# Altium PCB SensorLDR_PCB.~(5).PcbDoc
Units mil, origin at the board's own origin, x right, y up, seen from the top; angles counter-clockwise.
Board outline 6000 x 4000 mil, 2 copper layers (Top Layer, Bottom Layer); 24 components, 17 nets, 62 pads, 0 vias.
Unrouted connection lines stored in the file: 38.
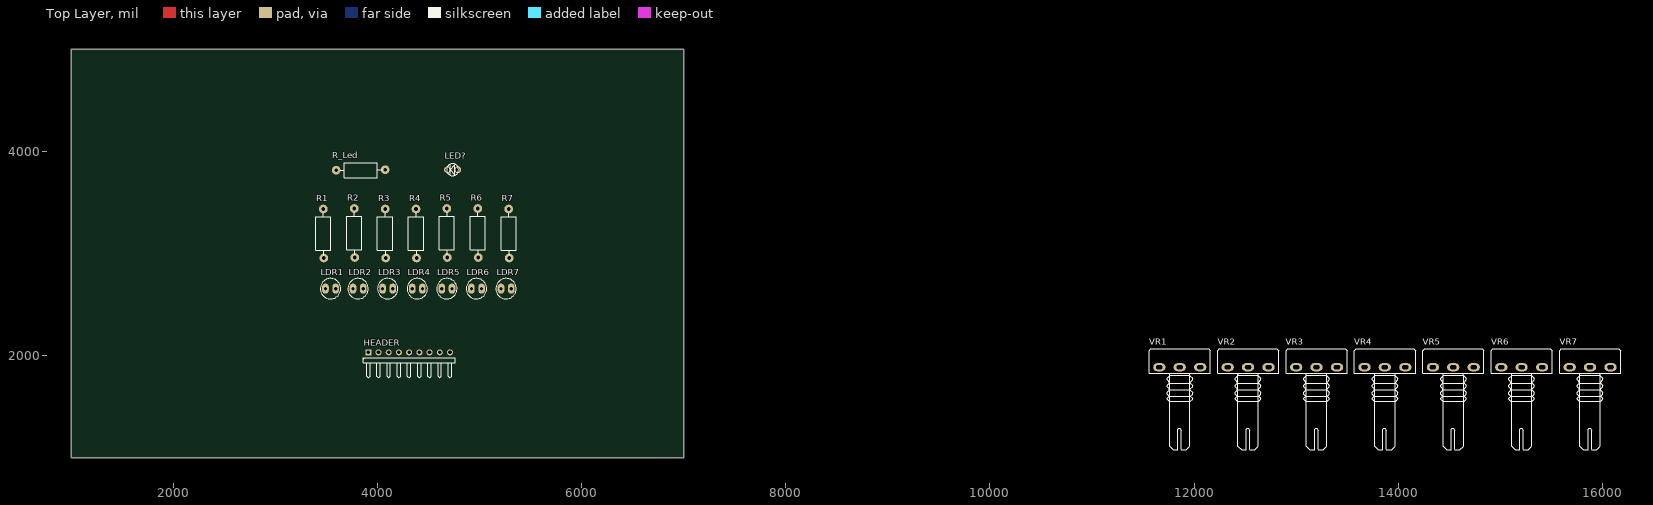
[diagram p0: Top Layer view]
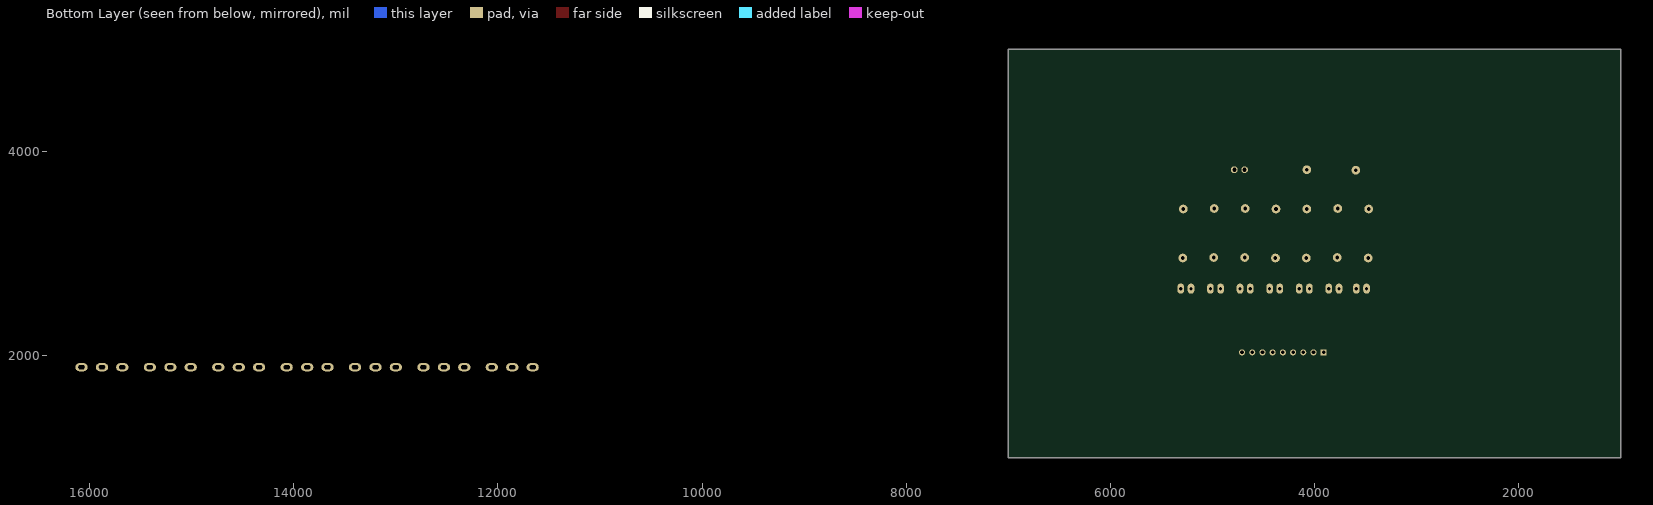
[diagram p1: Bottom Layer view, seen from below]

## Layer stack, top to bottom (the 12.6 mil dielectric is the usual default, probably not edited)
Top Solder: solder mask 0.4, Solder Resist, Dk 3.5
Top Layer: signal copper 1.4
Dielectric 1: dielectric 12.6, FR-4, Dk 4.8
Bottom Layer: signal copper 1.4
Bottom Solder: solder mask 0.4, Solder Resist, Dk 3.5

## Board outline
1000,1000 7000,1000 7000,5000 1000,5000

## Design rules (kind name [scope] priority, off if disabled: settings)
Clearance [All] p1: gap=10 ignorepadtopadclearanceinfootprint=FALSE except(0: Arc-Hole Track-Hole SMDPad-Hole THPad-Hole Via-Hole Fill-Hole Poly-Hole Region-Hole Text-Hole)
PolygonConnect [All] p1: connectstyle=Relief reliefconductorwidth=10 reliefentries=4 polygonreliefangle="90 Angle" airgapwidth=10
RoutingVias [All] p1: holewidth=28 width=50 viastyle="Through Hole" minholewidth=28 minwidth=50 maxholewidth=28 maxwidth=50
SolderMaskExpansion [All] p1: expansion=4
Width [All] p1: maxlimit=10 minlimit=10 preferedwidth=10
30 further rules are at their usual default settings.

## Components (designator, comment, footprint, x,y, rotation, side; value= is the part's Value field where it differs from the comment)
HEADER "Header 9H" HDR1X9H 3910,2030 r0 top
LDR1 "LDR" CDS 3490,2655 r0 top
LDR2 "LDR" CDS 3760,2655 r0 top
LDR3 "LDR" CDS 4050,2655 r0 top
LDR4 "LDR" CDS 4340,2655 r0 top
LDR5 "LDR" CDS 4630,2655 r0 top
LDR6 "LDR" CDS 4920,2655 r0 top
LDR7 "LDR" CDS 5210,2655 r0 top
LED? "LED" LED-3MM-YELLOW 4785,3820 r180 top value="LED 3 ly Single Colour"
R1 "Res" RES-1/2W 3470,3175 r90 top
R2 "Res" RES-1/2W 3772.5,3180 r90 top
R3 "Res" RES-1/2W 4075,3175 r90 top
R4 "Res" RES-1/2W 4377.5,3175 r90 top
R5 "Res" RES-1/2W 4680,3180 r90 top
R6 "Res" RES-1/2W 4982.5,3180 r90 top
R7 "Res" RES-1/2W 5285,3175 r90 top
R_Led "Res" RES-1/2W 3855,3815 r180 top
VR1 "50K" VR-S1 11860,1885 r0 top value="Volume 50k"
VR2 "50K" VR-S1 12530,1885 r0 top value="Volume 50k"
VR3 "50K" VR-S1 13200,1885 r0 top value="Volume 50k"
VR4 "50K" VR-S1 13870,1885 r0 top value="Volume 50k"
VR5 "50K" VR-S1 14540,1885 r0 top value="Volume 50k"
VR6 "50K" VR-S1 15210,1885 r0 top value="Volume 50k"
VR7 "50K" VR-S1 15880,1885 r0 top value="Volume 50k"

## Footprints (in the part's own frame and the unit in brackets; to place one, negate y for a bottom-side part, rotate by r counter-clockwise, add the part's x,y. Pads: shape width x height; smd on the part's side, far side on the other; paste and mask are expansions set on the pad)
CDS [mil] "QUANG TRO"
  oval 65x100 hole 32: 1(0,0) 2(100,0)
  silkscreen extent -50,-100 150,100, body extent -53,-80 153,89, height 138
HDR1X9H [mm] "Connector; Header; 9 Position; Right Angle"
  rect 1.5x1.5 hole 0.9: 1(0,0)
  round 1.5 hole 0.9: 2(2.54,0) 3(5.08,0) 4(7.62,0) 5(10.16,0) 6(12.7,0) 7(15.24,0) 8(17.78,0) 9(20.32,0)
  silkscreen extent -1.27,-6.35 21.59,-1.27
LED-3MM-YELLOW [mil]
  oct 65x65 hole 40: 1(0,0)
  round 65 hole 40: 2(100,0)
  silkscreen extent -9,-59 109,59, body extent -27,-77 117,80, height 181
RES-1/2W [mil]
  round 85 hole 35: 1(-220,-5) 2(260,0)
  silkscreen extent -195,-74 221,75, body extent -230,-60 270,56, height 121
VR-S1 [mil]
  oval 120x78.74 hole 40 slot 60 at 0 deg: 1(-200,0) 2(-1,0) 3(200,0)
  silkscreen extent -299,-810 300,179, body extent -310,-818 310,188, height 839

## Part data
HEADER: "Header, 9-Pin, Right Angle"
LDR1 LDR2 LDR3 LDR4 LDR5 LDR6 LDR7: "Quang Tro"
LED?: "LED Single colour Green and Red"
R1 R2 R3 R4 R5 R6 R7 R_Led: Manufacturer="Generic Components"
VR1 VR2 VR3 VR4 VR5 VR6 VR7: library part VR-S, "Var Resistor"

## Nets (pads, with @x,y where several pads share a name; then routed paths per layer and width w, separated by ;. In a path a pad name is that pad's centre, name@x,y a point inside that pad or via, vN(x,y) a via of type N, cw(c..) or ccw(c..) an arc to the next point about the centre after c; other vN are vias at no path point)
GND: HEADER.2 R1.2 R2.2 R3.2 R4.2 R5.2 R6.2 R7.2 R_Led.2
NetLDR1_1: LDR1.1 R1.1
NetLDR2_1: LDR2.1 R2.1
NetLDR3_1: LDR3.1 R3.1
NetLDR4_1: LDR4.1 R4.1
NetLDR5_1: LDR5.1 R5.1
NetLDR6_1: LDR6.1 R6.1
NetLDR7_1: LDR7.1 R7.1
NetLED?_2: LED?.2 R_Led.1
S1: HEADER.3 LDR1.2 VR1.2
S2: HEADER.4 LDR2.2 VR2.2
S3: HEADER.5 LDR3.2 VR3.2
S4: HEADER.6 LDR4.2 VR4.2
S5: HEADER.7 LDR5.2 VR5.2
S6: HEADER.8 LDR6.2 VR6.2
S7: HEADER.9 LDR7.2 VR7.2
VCC: HEADER.1 LED?.1 VR1.1 VR2.1 VR3.1 VR4.1 VR5.1 VR6.1 VR7.1
pads on no net: VR1.3 VR2.3 VR3.3 VR4.3 VR5.3 VR6.3 VR7.3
